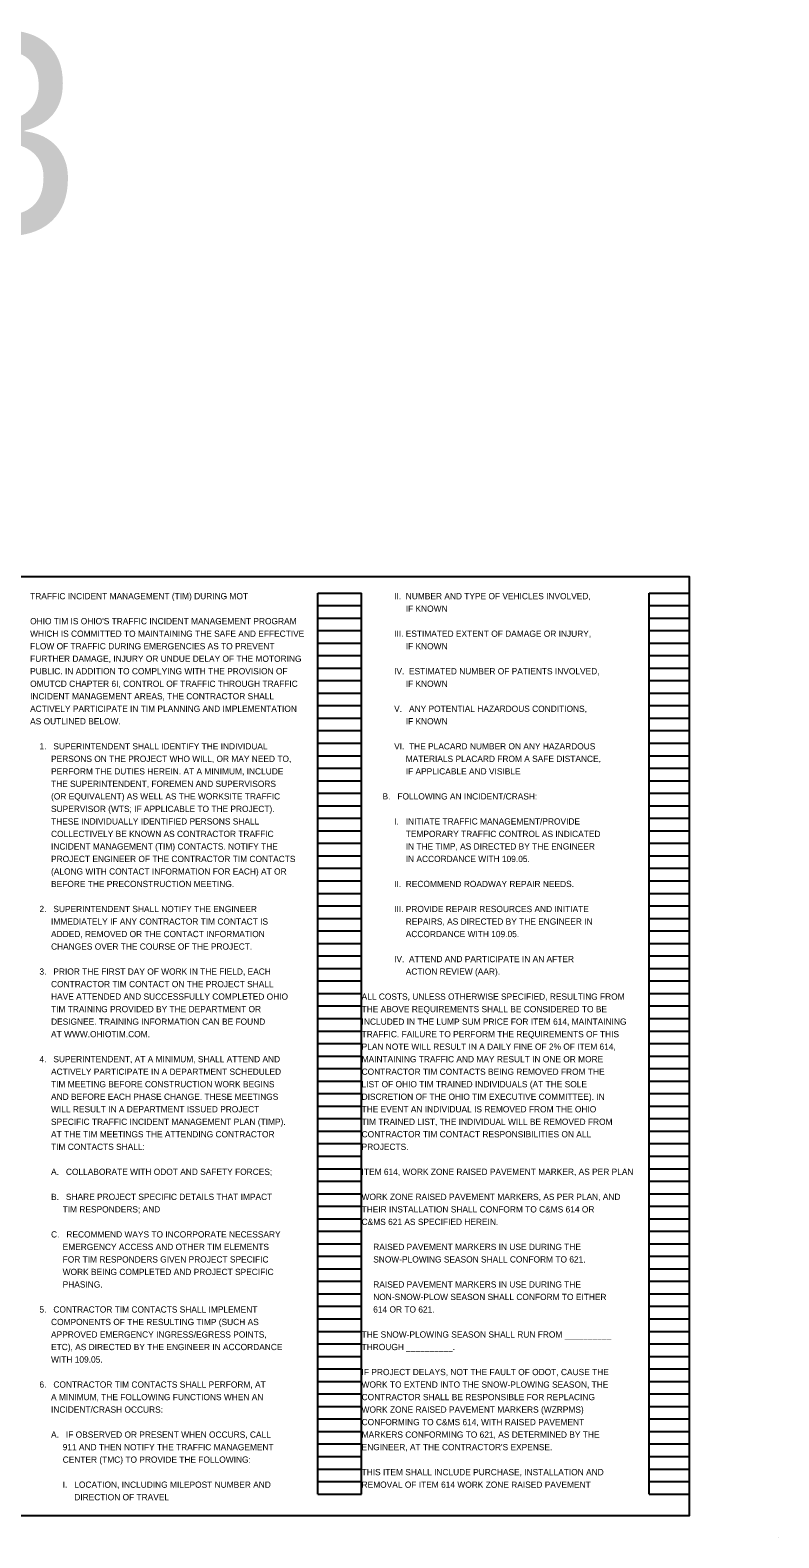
# Model space of a CAD drawing. Extents: x -34 to 2132911, y 0 to 658646.
# Drawn here: x 85.24 to 102, y 0 to 33.73 of the extents above; entities that cross this region are included whole.
import ezdxf

# ---------------------------------------------------------------- set-up
doc = ezdxf.new("R2010")
doc.units = 0
for name, color, linetype in [('Default', 7, 'Continuous'), ('SC_Scratch1', 7, 'Continuous'), ('SH_Data', 7, 'Continuous'), ('SH_Text', 7, 'Continuous')]:
    doc.layers.add(name, color=color, linetype=linetype)

msp = doc.modelspace()

# ---------------------------------------------------------------- linework, layer by layer
at = {"layer": 'SC_Scratch1'}
msp.add_lwpolyline([(69.5, 0.5), (100, 0.5), (100, 21.5), (69.5, 21.5)], close=True, dxfattribs=at)
at = {"layer": 'SH_Data'}
for p, q in [((91.68, 0.98), (91.68, 21.14)), ((91.68, 21.14), (92.66, 21.14)), ((92.66, 0.98), (92.66, 21.14)), ((99.1, 0.98), (99.1, 21.14)), ((99.1, 21.14), (100, 21.14)), ((100, 0.98), (100, 21.14)), ((91.68, 20.86), (92.66, 20.86)), ((91.68, 20.58), (92.66, 20.58)), ((99.1, 20.86), (100, 20.86)), ((99.1, 20.58), (100, 20.58)), ((91.68, 20.3), (92.66, 20.3)), ((99.1, 20.3), (100, 20.3)), ((91.68, 20.02), (92.66, 20.02)), ((99.1, 20.02), (100, 20.02)), ((91.68, 19.74), (92.66, 19.74)), ((99.1, 19.74), (100, 19.74)), ((91.68, 19.46), (92.66, 19.46)), ((99.1, 19.46), (100, 19.46)), ((91.68, 19.18), (92.66, 19.18)), ((91.68, 18.9), (92.66, 18.9)), ((99.1, 19.18), (100, 19.18)), ((99.1, 18.9), (100, 18.9)), ((91.68, 18.62), (92.66, 18.62)), ((99.1, 18.62), (100, 18.62)), ((91.68, 18.34), (92.66, 18.34)), ((99.1, 18.34), (100, 18.34)), ((91.68, 18.06), (92.66, 18.06)), ((99.1, 18.06), (100, 18.06)), ((91.68, 17.78), (92.66, 17.78)), ((99.1, 17.78), (100, 17.78)), ((91.68, 17.5), (92.66, 17.5)), ((91.68, 17.22), (92.66, 17.22)), ((99.1, 17.5), (100, 17.5)), ((99.1, 17.22), (100, 17.22)), ((91.68, 16.94), (92.66, 16.94)), ((99.1, 16.94), (100, 16.94)), ((91.68, 16.66), (92.66, 16.66)), ((99.1, 16.66), (100, 16.66)), ((91.68, 16.38), (92.66, 16.38)), ((99.1, 16.38), (100, 16.38)), ((91.68, 16.1), (92.66, 16.1)), ((99.1, 16.1), (100, 16.1)), ((91.68, 15.82), (92.66, 15.82)), ((91.68, 15.54), (92.66, 15.54)), ((99.1, 15.82), (100, 15.82)), ((99.1, 15.54), (100, 15.54)), ((91.68, 15.26), (92.66, 15.26)), ((99.1, 15.26), (100, 15.26)), ((91.68, 14.98), (92.66, 14.98)), ((99.1, 14.98), (100, 14.98)), ((91.68, 14.7), (92.66, 14.7)), ((99.1, 14.7), (100, 14.7)), ((91.68, 14.42), (92.66, 14.42)), ((99.1, 14.42), (100, 14.42)), ((91.68, 14.14), (92.66, 14.14)), ((91.68, 13.86), (92.66, 13.86)), ((99.1, 14.14), (100, 14.14)), ((99.1, 13.86), (100, 13.86)), ((91.68, 13.58), (92.66, 13.58)), ((99.1, 13.58), (100, 13.58)), ((91.68, 13.3), (92.66, 13.3)), ((99.1, 13.3), (100, 13.3)), ((91.68, 13.02), (92.66, 13.02)), ((99.1, 13.02), (100, 13.02)), ((91.68, 12.74), (92.66, 12.74)), ((99.1, 12.74), (100, 12.74)), ((91.68, 12.46), (92.66, 12.46)), ((91.68, 12.18), (92.66, 12.18)), ((99.1, 12.46), (100, 12.46)), ((99.1, 12.18), (100, 12.18)), ((91.68, 11.9), (92.66, 11.9)), ((99.1, 11.9), (100, 11.9)), ((91.68, 11.62), (92.66, 11.62)), ((99.1, 11.62), (100, 11.62)), ((91.68, 11.34), (92.66, 11.34)), ((99.1, 11.34), (100, 11.34)), ((91.68, 11.06), (92.66, 11.06)), ((99.1, 11.06), (100, 11.06)), ((91.68, 10.78), (92.66, 10.78)), ((91.68, 10.5), (92.66, 10.5)), ((99.1, 10.78), (100, 10.78)), ((99.1, 10.5), (100, 10.5)), ((91.68, 10.22), (92.66, 10.22)), ((99.1, 10.22), (100, 10.22)), ((91.68, 9.94), (92.66, 9.94)), ((99.1, 9.94), (100, 9.94)), ((91.68, 9.66), (92.66, 9.66)), ((99.1, 9.66), (100, 9.66)), ((91.68, 9.38), (92.66, 9.38)), ((99.1, 9.38), (100, 9.38)), ((91.68, 9.1), (92.66, 9.1)), ((91.68, 8.82), (92.66, 8.82)), ((99.1, 9.1), (100, 9.1)), ((99.1, 8.82), (100, 8.82)), ((91.68, 8.54), (92.66, 8.54)), ((99.1, 8.54), (100, 8.54)), ((91.68, 8.26), (92.66, 8.26)), ((99.1, 8.26), (100, 8.26)), ((91.68, 7.98), (92.66, 7.98)), ((99.1, 7.98), (100, 7.98)), ((91.68, 7.7), (92.66, 7.7)), ((99.1, 7.7), (100, 7.7)), ((91.68, 7.42), (92.66, 7.42)), ((91.68, 7.14), (92.66, 7.14)), ((99.1, 7.42), (100, 7.42)), ((99.1, 7.14), (100, 7.14)), ((91.68, 6.86), (92.66, 6.86)), ((99.1, 6.86), (100, 6.86)), ((91.68, 6.58), (92.66, 6.58)), ((99.1, 6.58), (100, 6.58)), ((91.68, 6.3), (92.66, 6.3)), ((99.1, 6.3), (100, 6.3)), ((91.68, 6.02), (92.66, 6.02)), ((91.68, 5.74), (92.66, 5.74)), ((99.1, 6.02), (100, 6.02)), ((99.1, 5.74), (100, 5.74)), ((91.68, 5.46), (92.66, 5.46)), ((99.1, 5.46), (100, 5.46)), ((91.68, 5.18), (92.66, 5.18)), ((99.1, 5.18), (100, 5.18)), ((91.68, 4.9), (92.66, 4.9)), ((99.1, 4.9), (100, 4.9)), ((91.68, 4.62), (92.66, 4.62)), ((99.1, 4.62), (100, 4.62)), ((91.68, 4.34), (92.66, 4.34)), ((91.68, 4.06), (92.66, 4.06)), ((99.1, 4.34), (100, 4.34)), ((99.1, 4.06), (100, 4.06)), ((91.68, 3.78), (92.66, 3.78)), ((99.1, 3.78), (100, 3.78)), ((91.68, 3.5), (92.66, 3.5)), ((99.1, 3.5), (100, 3.5)), ((91.68, 3.22), (92.66, 3.22)), ((99.1, 3.22), (100, 3.22)), ((91.68, 2.94), (92.66, 2.94)), ((99.1, 2.94), (100, 2.94)), ((91.68, 2.66), (92.66, 2.66)), ((91.68, 2.38), (92.66, 2.38)), ((99.1, 2.66), (100, 2.66)), ((99.1, 2.38), (100, 2.38)), ((91.68, 2.1), (92.66, 2.1)), ((99.1, 2.1), (100, 2.1)), ((91.68, 1.82), (92.66, 1.82)), ((99.1, 1.82), (100, 1.82)), ((91.68, 1.54), (92.66, 1.54)), ((99.1, 1.54), (100, 1.54)), ((91.68, 1.26), (92.66, 1.26)), ((99.1, 1.26), (100, 1.26)), ((91.68, 0.98), (92.66, 0.98)), ((99.1, 0.98), (100, 0.98)), ((102, 0), (102, 0))]:
    msp.add_line(p, q, dxfattribs=at)

# ---------------------------------------------------------------- texts
at = {"layer": 'Default'}
msp.add_text('3', height=4.48, dxfattribs=at).set_placement((83.018, 29.186))
at = {"layer": 'SH_Text'}
for s, p in [('TRAFFIC INCIDENT MANAGEMENT (TIM) DURING MOT', (85.24, 21)), ('              II.  NUMBER AND TYPE OF VEHICLES INVOLVED,', (92.66, 21)), ("OHIO TIM IS OHIO'S TRAFFIC INCIDENT MANAGEMENT PROGRAM", (85.24, 20.44)), ('                   IF KNOWN', (92.66, 20.72)), ('WHICH IS COMMITTED TO MAINTAINING THE SAFE AND EFFECTIVE', (85.24, 20.16)), ('              III. ESTIMATED EXTENT OF DAMAGE OR INJURY,', (92.66, 20.16)), ('FLOW OF TRAFFIC DURING EMERGENCIES AS TO PREVENT', (85.24, 19.88)), ('                   IF KNOWN', (92.66, 19.88)), ('FURTHER DAMAGE, INJURY OR UNDUE DELAY OF THE MOTORING', (85.24, 19.6)), ('PUBLIC. IN ADDITION TO COMPLYING WITH THE PROVISION OF', (85.24, 19.32)), ('              IV.  ESTIMATED NUMBER OF PATIENTS INVOLVED,', (92.66, 19.32)), ('OMUTCD CHAPTER 6I, CONTROL OF TRAFFIC THROUGH TRAFFIC', (85.24, 19.04)), ('INCIDENT MANAGEMENT AREAS, THE CONTRACTOR SHALL', (85.24, 18.76)), ('                   IF KNOWN', (92.66, 19.04)), ('ACTIVELY PARTICIPATE IN TIM PLANNING AND IMPLEMENTATION', (85.24, 18.48)), ('              V.   ANY POTENTIAL HAZARDOUS CONDITIONS,', (92.66, 18.48)), ('AS OUTLINED BELOW.', (85.24, 18.2)), ('                   IF KNOWN', (92.66, 18.2)), ('    1.   SUPERINTENDENT SHALL IDENTIFY THE INDIVIDUAL', (85.24, 17.64)), ('              VI.  THE PLACARD NUMBER ON ANY HAZARDOUS', (92.66, 17.64)), ('         PERSONS ON THE PROJECT WHO WILL, OR MAY NEED TO,', (85.24, 17.36)), ('         PERFORM THE DUTIES HEREIN. AT A MINIMUM, INCLUDE', (85.24, 17.08)), ('                   MATERIALS PLACARD FROM A SAFE DISTANCE,', (92.66, 17.36)), ('                   IF APPLICABLE AND VISIBLE', (92.66, 17.08)), ('         THE SUPERINTENDENT, FOREMEN AND SUPERVISORS', (85.24, 16.8)), ('         (OR EQUIVALENT) AS WELL AS THE WORKSITE TRAFFIC', (85.24, 16.52)), ('         B.   FOLLOWING AN INCIDENT/CRASH:', (92.66, 16.52)), ('         SUPERVISOR (WTS; IF APPLICABLE TO THE PROJECT).', (85.24, 16.24)), ('         THESE INDIVIDUALLY IDENTIFIED PERSONS SHALL', (85.24, 15.96)), ('              I.   INITIATE TRAFFIC MANAGEMENT/PROVIDE', (92.66, 15.96)), ('         COLLECTIVELY BE KNOWN AS CONTRACTOR TRAFFIC', (85.24, 15.68)), ('         INCIDENT MANAGEMENT (TIM) CONTACTS. NOTIFY THE', (85.24, 15.4)), ('                   TEMPORARY TRAFFIC CONTROL AS INDICATED', (92.66, 15.68)), ('                   IN THE TIMP, AS DIRECTED BY THE ENGINEER', (92.66, 15.4)), ('         PROJECT ENGINEER OF THE CONTRACTOR TIM CONTACTS', (85.24, 15.12)), ('                   IN ACCORDANCE WITH 109.05.', (92.66, 15.12)), ('         (ALONG WITH CONTACT INFORMATION FOR EACH) AT OR', (85.24, 14.84)), ('         BEFORE THE PRECONSTRUCTION MEETING.', (85.24, 14.56)), ('              II.  RECOMMEND ROADWAY REPAIR NEEDS.', (92.66, 14.56)), ('    2.   SUPERINTENDENT SHALL NOTIFY THE ENGINEER', (85.24, 14)), ('         IMMEDIATELY IF ANY CONTRACTOR TIM CONTACT IS', (85.24, 13.72)), ('              III. PROVIDE REPAIR RESOURCES AND INITIATE', (92.66, 14)), ('                   REPAIRS, AS DIRECTED BY THE ENGINEER IN', (92.66, 13.72)), ('         ADDED, REMOVED OR THE CONTACT INFORMATION', (85.24, 13.44)), ('                   ACCORDANCE WITH 109.05.', (92.66, 13.44)), ('         CHANGES OVER THE COURSE OF THE PROJECT.', (85.24, 13.16)), ('              IV.  ATTEND AND PARTICIPATE IN AN AFTER', (92.66, 12.88)), ('    3.   PRIOR THE FIRST DAY OF WORK IN THE FIELD, EACH', (85.24, 12.6)), ('                   ACTION REVIEW (AAR).', (92.66, 12.6)), ('         CONTRACTOR TIM CONTACT ON THE PROJECT SHALL', (85.24, 12.32)), ('         HAVE ATTENDED AND SUCCESSFULLY COMPLETED OHIO', (85.24, 12.04)), ('ALL COSTS, UNLESS OTHERWISE SPECIFIED, RESULTING FROM', (92.66, 12.04)), ('         TIM TRAINING PROVIDED BY THE DEPARTMENT OR', (85.24, 11.76)), ('THE ABOVE REQUIREMENTS SHALL BE CONSIDERED TO BE', (92.66, 11.76)), ('         DESIGNEE. TRAINING INFORMATION CAN BE FOUND', (85.24, 11.48)), ('INCLUDED IN THE LUMP SUM PRICE FOR ITEM 614, MAINTAINING', (92.66, 11.48)), ('         AT WWW.OHIOTIM.COM.', (85.24, 11.2)), ('TRAFFIC. FAILURE TO PERFORM THE REQUIREMENTS OF THIS', (92.66, 11.2)), ('PLAN NOTE WILL RESULT IN A DAILY FINE OF 2% OF ITEM 614,', (92.66, 10.92)), ('    4.   SUPERINTENDENT, AT A MINIMUM, SHALL ATTEND AND', (85.24, 10.64)), ('         ACTIVELY PARTICIPATE IN A DEPARTMENT SCHEDULED', (85.24, 10.36)), ('CONTRACTOR TIM CONTACTS BEING REMOVED FROM THE', (92.66, 10.36)), ('MAINTAINING TRAFFIC AND MAY RESULT IN ONE OR MORE', (92.66, 10.64)), ('         TIM MEETING BEFORE CONSTRUCTION WORK BEGINS', (85.24, 10.08)), ('LIST OF OHIO TIM TRAINED INDIVIDUALS (AT THE SOLE', (92.66, 10.08)), ('         AND BEFORE EACH PHASE CHANGE. THESE MEETINGS', (85.24, 9.8)), ('DISCRETION OF THE OHIO TIM EXECUTIVE COMMITTEE). IN', (92.66, 9.8)), ('         WILL RESULT IN A DEPARTMENT ISSUED PROJECT', (85.24, 9.52)), ('THE EVENT AN INDIVIDUAL IS REMOVED FROM THE OHIO', (92.66, 9.52)), ('         SPECIFIC TRAFFIC INCIDENT MANAGEMENT PLAN (TIMP).', (85.24, 9.24)), ('TIM TRAINED LIST, THE INDIVIDUAL WILL BE REMOVED FROM', (92.66, 9.24)), ('         AT THE TIM MEETINGS THE ATTENDING CONTRACTOR', (85.24, 8.96)), ('         TIM CONTACTS SHALL:', (85.24, 8.68)), ('CONTRACTOR TIM CONTACT RESPONSIBILITIES ON ALL', (92.66, 8.96)), ('PROJECTS.', (92.66, 8.68)), ('         A.   COLLABORATE WITH ODOT AND SAFETY FORCES;', (85.24, 8.12)), ('ITEM 614, WORK ZONE RAISED PAVEMENT MARKER, AS PER PLAN', (92.66, 8.12)), ('         B.   SHARE PROJECT SPECIFIC DETAILS THAT IMPACT', (85.24, 7.56)), ('              TIM RESPONDERS; AND', (85.24, 7.28)), ('WORK ZONE RAISED PAVEMENT MARKERS, AS PER PLAN, AND', (92.66, 7.56)), ('THEIR INSTALLATION SHALL CONFORM TO C&MS 614 OR', (92.66, 7.28)), ('C&MS 621 AS SPECIFIED HEREIN.', (92.66, 7)), ('         C.   RECOMMEND WAYS TO INCORPORATE NECESSARY', (85.24, 6.72)), ('              EMERGENCY ACCESS AND OTHER TIM ELEMENTS', (85.24, 6.44)), ('     RAISED PAVEMENT MARKERS IN USE DURING THE', (92.66, 6.44)), ('              FOR TIM RESPONDERS GIVEN PROJECT SPECIFIC', (85.24, 6.16)), ('     SNOW-PLOWING SEASON SHALL CONFORM TO 621.', (92.66, 6.16)), ('              WORK BEING COMPLETED AND PROJECT SPECIFIC', (85.24, 5.88)), ('              PHASING.', (85.24, 5.6)), ('     RAISED PAVEMENT MARKERS IN USE DURING THE', (92.66, 5.6)), ('     NON-SNOW-PLOW SEASON SHALL CONFORM TO EITHER', (92.66, 5.32)), ('    5.   CONTRACTOR TIM CONTACTS SHALL IMPLEMENT', (85.24, 5.04)), ('     614 OR TO 621.', (92.66, 5.04)), ('         COMPONENTS OF THE RESULTING TIMP (SUCH AS', (85.24, 4.76)), ('         APPROVED EMERGENCY INGRESS/EGRESS POINTS,', (85.24, 4.48)), ('THE SNOW-PLOWING SEASON SHALL RUN FROM __________', (92.66, 4.48)), ('         WITH 109.05.', (85.24, 3.92)), ('         ETC), AS DIRECTED BY THE ENGINEER IN ACCORDANCE', (85.24, 4.2)), ('THROUGH __________.', (92.66, 4.2)), ('IF PROJECT DELAYS, NOT THE FAULT OF ODOT, CAUSE THE', (92.66, 3.64)), ('    6.   CONTRACTOR TIM CONTACTS SHALL PERFORM, AT', (85.24, 3.36)), ('WORK TO EXTEND INTO THE SNOW-PLOWING SEASON, THE', (92.66, 3.36)), ('         A MINIMUM, THE FOLLOWING FUNCTIONS WHEN AN', (85.24, 3.08)), ('CONTRACTOR SHALL BE RESPONSIBLE FOR REPLACING', (92.66, 3.08)), ('         INCIDENT/CRASH OCCURS:', (85.24, 2.8)), ('WORK ZONE RAISED PAVEMENT MARKERS (WZRPMS)', (92.66, 2.8)), ('         A.   IF OBSERVED OR PRESENT WHEN OCCURS, CALL', (85.24, 2.24)), ('CONFORMING TO C&MS 614, WITH RAISED PAVEMENT', (92.66, 2.52)), ('MARKERS CONFORMING TO 621, AS DETERMINED BY THE', (92.66, 2.24)), ('              911 AND THEN NOTIFY THE TRAFFIC MANAGEMENT', (85.24, 1.96)), ("ENGINEER, AT THE CONTRACTOR'S EXPENSE.", (92.66, 1.96)), ('              CENTER (TMC) TO PROVIDE THE FOLLOWING:', (85.24, 1.68)), ('THIS ITEM SHALL INCLUDE PURCHASE, INSTALLATION AND', (92.66, 1.4)), ('              I.   LOCATION, INCLUDING MILEPOST NUMBER AND', (85.24, 1.12)), ('REMOVAL OF ITEM 614 WORK ZONE RAISED PAVEMENT', (92.66, 1.12)), ('                   DIRECTION OF TRAVEL', (85.24, 0.84))]:
    msp.add_text(s, height=0.14, dxfattribs=at).set_placement(p)

doc.saveas('drawing.dxf')
